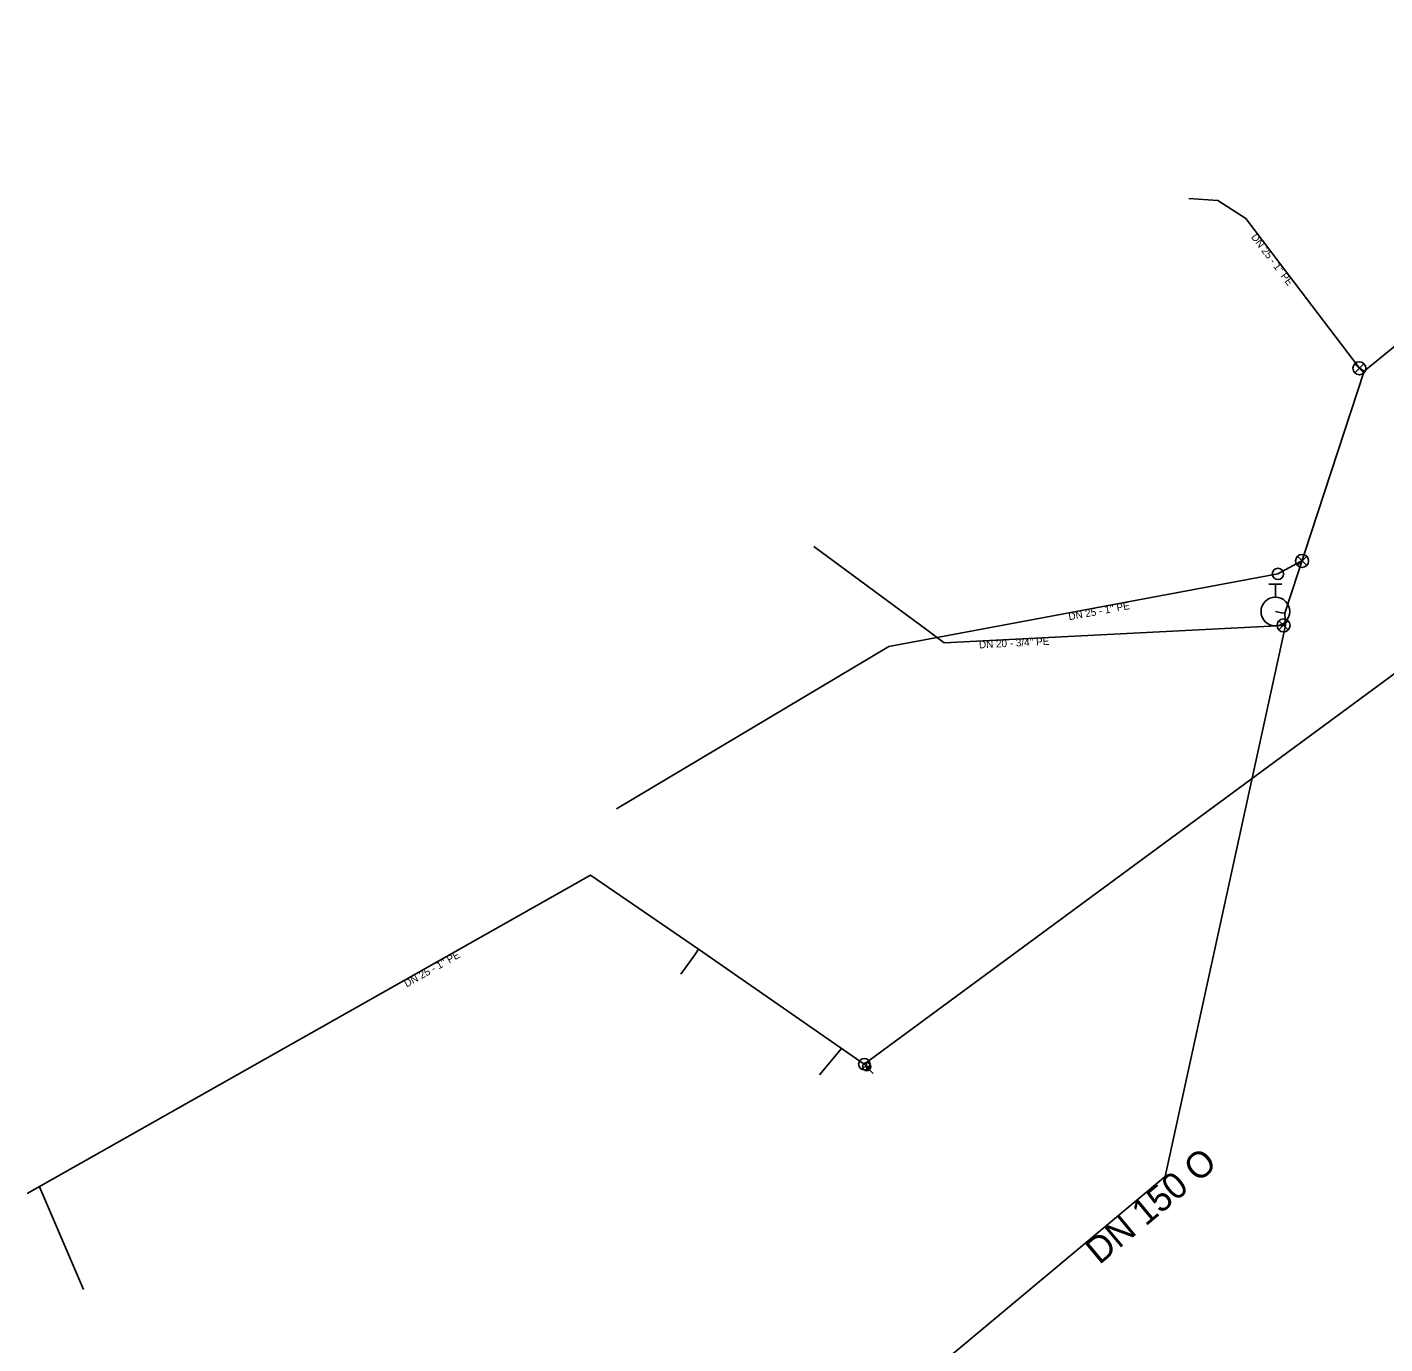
# Model space of a CAD drawing. Extents: x -451555 to -451079, y -1102113 to -1101586.
# Drawn here: x -451527.2 to -451443.8, y -1101795.5 to -1101714.6 of the extents above; entities that cross this region are included whole.
import ezdxf

# ---------------------------------------------------------------- set-up
doc = ezdxf.new("R2010")
doc.units = 0
for name, color, linetype in [('_hydrantova_odbocka_', 7, 'Continuous'), ('_kalosvod_', 7, 'Continuous'), ('_pripojka_prevzato_z_dokumentace_', 7, 'Continuous'), ('_pripojka_priblizne_', 7, 'Continuous'), ('_voda_smvak_prevzato_z_dokumentace_', 7, 'Continuous'), ('Default', 7, 'Continuous'), ('MoLevel 27', 7, 'Continuous'), ('MoLevel 28', 7, 'Continuous'), ('MoLevel 30', 7, 'Continuous'), ('MoLevel 32', 7, 'Continuous'), ('MoLevel 46', 7, 'Continuous'), ('MoLevel 53', 7, 'Continuous'), ('MoLevel 55', 7, 'Continuous')]:
    doc.layers.add(name, color=color, linetype=linetype)

# ---------------------------------------------------------------- blocks, each defined once
blk = doc.blocks.new('_uzaver_')
at = {"layer": 'Default'}
for p, q in [((-0.000035, -0.000035), (0.000035, 0.000035)), ((0.000035, -0.000035), (-0.000035, 0.000035))]:
    blk.add_line(p, q, dxfattribs=at)
for radius in [0.00005, 0.0000025]:
    blk.add_circle((0, 0), radius, dxfattribs=at)
blk = doc.blocks.new('_uzaver_pripojka_')
at = {"layer": 'Default'}
for p, q in [((-0.000035, -0.000035), (0.000035, 0.000035)), ((0.000035, -0.000035), (-0.000035, 0.000035))]:
    blk.add_line(p, q, dxfattribs=at)
for radius in [0.00005, 0.0000025]:
    blk.add_circle((0, 0), radius, dxfattribs=at)
blk = doc.blocks.new('_hydrant_voda_')
at = {"layer": 'Default'}
for p, q in [((-0.0000225, 0.000095), (0.0000225, 0.000095)), ((0, 0.000095), (0, 0.00005))]:
    blk.add_line(p, q, dxfattribs=at)
blk.add_circle((0, 0), 0.00005, dxfattribs=at)
blk = doc.blocks.new('_sachta_voda_')
at = {"layer": 'Default'}
blk.add_circle((0, 0), 0.000035, dxfattribs=at)

msp = doc.modelspace()

# ---------------------------------------------------------------- linework, layer by layer
at = {"layer": '_hydrantova_odbocka_'}
msp.add_lwpolyline([(-451450.48, -1101750.51), (-451450.11, -1101750.58), (-451449.89, -1101750.62)], dxfattribs=at)
at = {"layer": '_kalosvod_'}
msp.add_lwpolyline([(-451475.73, -1101778.32), (-451475.59, -1101778.465), (-451475.178, -1101778.879)], dxfattribs=at)
at = {"layer": '_pripojka_prevzato_z_dokumentace_'}
msp.add_line((-451478.83, -1101746.51), (-451471.885, -1101751.643), dxfattribs=at)
for points in [[(-451449.666, -1101729.835), (-451452.3, -1101726.36), (-451454.01, -1101725.26), (-451455.79, -1101725.13)], [(-451445.03, -1101735.74), (-451445.32, -1101735.57), (-451449.666, -1101729.835)], [(-451471.885, -1101751.643), (-451470.82, -1101752.43), (-451449.98, -1101751.36), (-451449.86, -1101751.37)], [(-451485.91, -1101771.25), (-451486.11, -1101771.53), (-451487, -1101772.78)]]:
    msp.add_lwpolyline(points, dxfattribs=at)
at = {"layer": '_pripojka_priblizne_'}
for p, q in [((-451478.49, -1101778.977), (-451477.134, -1101777.345)), ((-451523.692, -1101792.157), (-451526.403, -1101785.844))]:
    msp.add_line(p, q, dxfattribs=at)
for points in [[(-451448.838, -1101747.399), (-451448.937, -1101747.443), (-451450.324, -1101748.202), (-451450.324, -1101748.202)], [(-451450.324, -1101748.202), (-451474.219, -1101752.654), (-451490.961, -1101762.624)], [(-451475.73, -1101778.32), (-451485.91, -1101771.25), (-451492.54, -1101766.7), (-451527.154, -1101786.268)]]:
    msp.add_lwpolyline(points, dxfattribs=at)
at = {"layer": '_voda_smvak_prevzato_z_dokumentace_'}
msp.add_line((-451391.04, -1101715.88), (-451475.73, -1101778.32), dxfattribs=at)
for points in [[(-451352.37, -1101668.69), (-451374.89, -1101685.01), (-451391.639, -1101696.056), (-451420.33, -1101714.98), (-451434, -1101726.73), (-451445.03, -1101735.74), (-451449.89, -1101750.62)], [(-451449.89, -1101750.62), (-451449.86, -1101751.37), (-451457.26, -1101785.22), (-451475.77, -1101800.67), (-451484.25, -1101806.83), (-451484.69, -1101807.39), (-451484.62, -1101808.13)]]:
    msp.add_lwpolyline(points, dxfattribs=at)

# ---------------------------------------------------------------- block references
at = {"layer": 'MoLevel 27', "xscale": 5000, "yscale": 5000, "rotation": -37.40535663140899}
msp.add_blockref('_uzaver_', (-451475.59, -1101778.465), dxfattribs=at)
at = {"layer": 'MoLevel 28', "xscale": 17636.68430335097, "yscale": 17636.68430335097}
msp.add_blockref('_hydrant_voda_', (-451450.48, -1101750.51), dxfattribs=at)
at = {"layer": 'MoLevel 30', "xscale": 10000, "yscale": 10000}
for p in [(-451450.324, -1101748.202), (-451475.73, -1101778.32)]:
    msp.add_blockref('_sachta_voda_', p, dxfattribs=at)
at = {"layer": 'MoLevel 53', "xscale": 7999.999999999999, "yscale": 7999.999999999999}
for p in [(-451445.32, -1101735.57), (-451448.838, -1101747.399), (-451449.98, -1101751.36)]:
    msp.add_blockref('_uzaver_pripojka_', p, dxfattribs=at)

# ---------------------------------------------------------------- texts
at = {"layer": 'MoLevel 32'}
for rotation, p in [(10.55495, (-451463.147, -1101751.054)), (29.4806, (-451503.84, -1101773.611))]:
    msp.add_text("DN 25 - 1'' PE", height=0.455, rotation=rotation, dxfattribs=at).set_placement(p)
at = {"layer": 'MoLevel 46'}
msp.add_text('DN 150 O', height=1.6049, rotation=39.85121, dxfattribs=at).set_placement((-451461.291, -1101790.675))
at = {"layer": 'MoLevel 55'}
for s, rotation, p in [("DN 25 - 1'' PE", 307.15747, (-451451.997, -1101727.513)), ("DN 20 - 3/4'' PE", 2.93919, (-451468.676, -1101752.776))]:
    msp.add_text(s, height=0.455, rotation=rotation, dxfattribs=at).set_placement(p)

doc.saveas('drawing.dxf')
